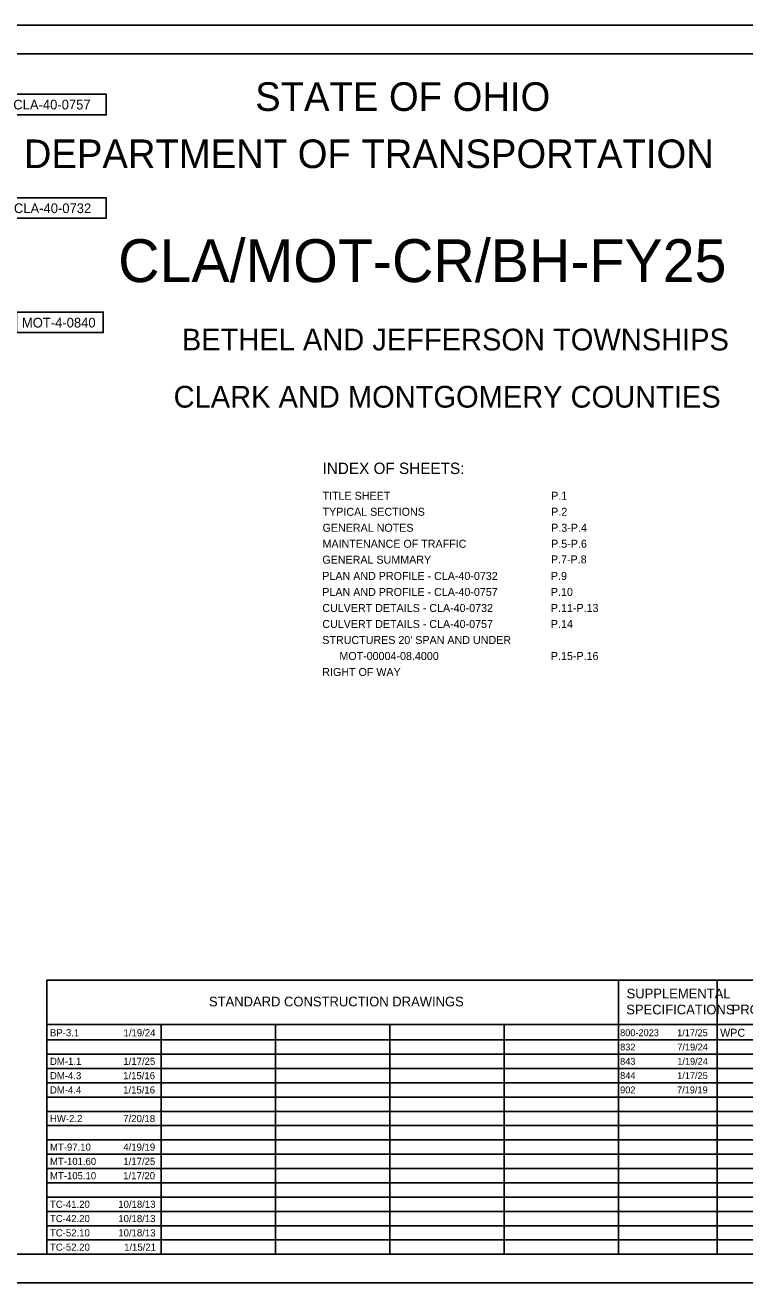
# Model space of a CAD drawing. Extents: x 0 to 34, y 0 to 22.
# Drawn here: x 9.77 to 22.36, y 0 to 22 of the extents above; entities that cross this region are included whole.
import ezdxf

# ---------------------------------------------------------------- set-up
doc = ezdxf.new("R2010")
doc.units = 0
for name, color, linetype in [('SH_Border', 7, 'Continuous'), ('SH_Cut_Line', 7, 'Continuous'), ('SH_Data', 7, 'Continuous'), ('SH_Text', 7, 'Continuous')]:
    doc.layers.add(name, color=color, linetype=linetype)

msp = doc.modelspace()

# ---------------------------------------------------------------- linework, layer by layer
at = {"layer": 'SH_Border'}
msp.add_lwpolyline([(1.5, 21.5), (33.5, 21.5), (33.5, 0.5), (1.5, 0.5)], close=True, dxfattribs=at)
at = {"layer": 'SH_Cut_Line'}
msp.add_lwpolyline([(0, 0), (34, 0), (34, 22), (0, 22)], close=True, dxfattribs=at)
at = {"layer": 'SH_Data'}
for p, q in [((10.15, 5.292), (23.6, 5.292)), ((10.15, 0.5), (10.15, 5.292)), ((20.15, 0.5), (20.15, 5.292)), ((21.875, 0.5), (21.875, 5.292)), ((10.15, 4.521), (23.6, 4.521)), ((12.15, 0.5), (12.15, 4.521)), ((14.15, 0.5), (14.15, 4.521)), ((16.15, 0.5), (16.15, 4.521)), ((18.15, 0.5), (18.15, 4.521)), ((10.15, 4.25), (23.6, 4.25)), ((10.15, 4), (23.6, 4)), ((10.15, 3.75), (23.6, 3.75)), ((10.15, 3.5), (23.6, 3.5)), ((10.15, 3.25), (23.6, 3.25)), ((10.15, 3), (23.6, 3)), ((10.15, 2.75), (23.6, 2.75)), ((10.15, 2.5), (23.6, 2.5)), ((10.15, 2.25), (23.6, 2.25)), ((10.15, 2), (23.6, 2)), ((10.15, 1.75), (23.6, 1.75)), ((10.15, 1.5), (23.6, 1.5)), ((10.15, 1.25), (23.6, 1.25)), ((10.15, 1), (23.6, 1)), ((10.15, 0.75), (23.6, 0.75))]:
    msp.add_line(p, q, dxfattribs=at)
at = {"layer": 'SH_Text'}
for points in [[(9.478, 20.79), (11.188, 20.79), (11.188, 20.43), (9.478, 20.43)], [(9.477, 18.982), (11.187, 18.982), (11.187, 18.622), (9.477, 18.622)], [(9.617, 16.981), (11.138, 16.981), (11.138, 16.621), (9.617, 16.621)]]:
    msp.add_lwpolyline(points, close=True, dxfattribs=at)

# ---------------------------------------------------------------- texts
at = {"layer": 'SH_Data'}
for s, p in [('BP-3.1', (10.205, 4.312)), ('1/19/24', (11.492, 4.312)), ('DM-1.1', (10.205, 3.812)), ('1/17/25', (11.489, 3.812)), ('DM-4.3', (10.205, 3.562)), ('1/15/16', (11.485, 3.562)), ('DM-4.4', (10.205, 3.312)), ('1/15/16', (11.485, 3.312)), ('HW-2.2', (10.205, 2.812)), ('7/20/18', (11.487, 2.812)), ('MT-97.10', (10.205, 2.312)), ('4/19/19', (11.488, 2.312)), ('MT-101.60', (10.205, 2.062)), ('1/17/25', (11.489, 2.062)), ('MT-105.10', (10.205, 1.812)), ('1/17/20', (11.486, 1.812)), ('TC-41.20', (10.205, 1.312)), ('10/18/13', (11.4, 1.312)), ('TC-42.20', (10.205, 1.062)), ('10/18/13', (11.4, 1.062)), ('TC-52.10', (10.205, 0.812)), ('10/18/13', (11.4, 0.812)), ('TC-52.20', (10.205, 0.562)), ('1/15/21', (11.502, 0.562))]:
    msp.add_text(s, height=0.125, dxfattribs=at).set_placement(p)
at = {"layer": 'SH_Text'}
for s, height, p in [('STATE OF OHIO', 0.5, (13.795, 20.5)), ('CLA-40-0757', 0.17, (9.563, 20.525)), ('DEPARTMENT OF TRANSPORTATION', 0.5, (9.747, 19.5)), ('CLA-40-0732', 0.17, (9.574, 18.712)), ('CLA/MOT-CR/BH-FY25', 0.75, (11.397, 17.505)), ('MOT-4-0840', 0.17, (9.714, 16.711)), ('BETHEL AND JEFFERSON TOWNSHIPS', 0.38, (12.512, 16.31)), ('CLARK AND MONTGOMERY COUNTIES', 0.38, (12.368, 15.31)), ('INDEX OF SHEETS:', 0.2, (14.974, 14.148)), ('TITLE SHEET', 0.14, (14.974, 13.698)), ('P.1', 0.14, (18.974, 13.698)), ('TYPICAL SECTIONS', 0.14, (14.974, 13.418)), ('P.2', 0.14, (18.974, 13.418)), ('GENERAL NOTES', 0.14, (14.974, 13.138)), ('P.3-P.4', 0.14, (18.974, 13.138)), ('MAINTENANCE OF TRAFFIC', 0.14, (14.974, 12.858)), ('P.5-P.6', 0.14, (18.974, 12.858)), ('GENERAL SUMMARY', 0.14, (14.97, 12.58)), ('P.7-P.8', 0.14, (18.97, 12.585)), ('PLAN AND PROFILE - CLA-40-0732', 0.14, (14.969, 12.295)), ('P.9', 0.14, (18.969, 12.295)), ('PLAN AND PROFILE - CLA-40-0757', 0.14, (14.969, 12.015)), ('P.10', 0.14, (18.969, 12.015)), ('CULVERT DETAILS - CLA-40-0732', 0.14, (14.969, 11.735)), ('P.11-P.13', 0.14, (18.969, 11.735)), ('CULVERT DETAILS - CLA-40-0757', 0.14, (14.969, 11.455)), ('P.14', 0.14, (18.969, 11.455)), ("STRUCTURES 20' SPAN AND UNDER", 0.14, (14.969, 11.175)), ('MOT-00004-08.4000', 0.14, (15.268, 10.895)), ('P.15-P.16', 0.14, (18.969, 10.895)), ('RIGHT OF WAY', 0.14, (14.969, 10.615)), ('SUPPLEMENTAL', 0.17, (20.293, 4.976)), ('STANDARD CONSTRUCTION DRAWINGS', 0.17, (12.986, 4.836)), ('SPECIFICATIONS', 0.17, (20.287, 4.696)), ('PROVISIONS', 0.17, (22.132, 4.696)), ('800-2023', 0.12, (20.18, 4.315)), ('1/17/25', 0.12, (21.178, 4.315)), ('WPC', 0.14, (21.93, 4.305)), ('832', 0.12, (20.18, 4.065)), ('7/19/24', 0.12, (21.18, 4.065)), ('843', 0.12, (20.18, 3.815)), ('1/19/24', 0.12, (21.18, 3.815)), ('844', 0.12, (20.18, 3.565)), ('1/17/25', 0.12, (21.178, 3.565)), ('902', 0.12, (20.18, 3.315)), ('7/19/19', 0.12, (21.176, 3.315))]:
    msp.add_text(s, height=height, dxfattribs=at).set_placement(p)

doc.saveas('drawing.dxf')
